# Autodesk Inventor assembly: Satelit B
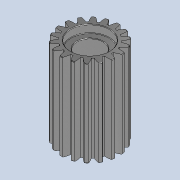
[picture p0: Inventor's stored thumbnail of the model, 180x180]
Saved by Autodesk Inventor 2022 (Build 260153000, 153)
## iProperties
Created: 2025-05
Part Number: Satelit B
Document SubType Name: Assembly
Designer: jbart
Mass: 1135.55 g
Surface Area: 1687.53 cm^2
Volume: 1135.55 cm^3
Density: 1 g/cm^3
Author: jbart
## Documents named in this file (2)
- C:\Users\jbart\OneDrive\Dokumenty\Inventor\Převodovka navijáku\Satelit B.iam
- C:\Users\jbart\OneDrive\Dokumenty\Inventor\Převodovka navijáku\Satelit B\Design Accelerator\Čelní ozubená kola1.iam
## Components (1 placed, 1 different names)
1. Čelní ozubená kola:1 [sub-assembly]
